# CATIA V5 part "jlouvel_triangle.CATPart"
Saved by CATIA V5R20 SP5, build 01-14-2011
Part number: Pièce 4_triangle
Bounding box of the stored display mesh (mm): x 0 to 5, y -113.66 to 130.843, z -78.426 to 5
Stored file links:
  E:\IAO_2010\iao\IAO_MMS_Groupe2\IAO_MMS_Groupe2\OK\jlouvel\jlouvel_iao\pièces cao catia ifma\jlouvel_triangle.CATPart
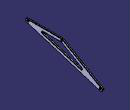
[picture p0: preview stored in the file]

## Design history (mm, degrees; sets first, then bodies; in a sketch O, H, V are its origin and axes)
Body1 (main body)
  Sketch1 on yz-plane, origin (0, 0, 0), H (0, 1, 0), V (0, 0, 1)
    line L1 (-113.6603, 5) -> (1.3397, 5)
    line L2 (1.3397, 5) -> (131.2436, -70)
    line L3 (131.2436, -70) -> (126.2436, -78.6603)
    line L4 (126.2436, -78.6603) -> (28.9711, -22.5)
    line L5 (28.9711, -22.5) -> (-1.3397, -5)
    line L6 (-1.3397, -5) -> (-113.6603, -5)
    line L7 (-113.6603, -5) -> (-113.6603, 5)
    length L7 = 10
    length L3 = 10
    length L1 = 115
    angle L2 L1 = 150
    distance L2 O = 5
    angle L5 L6 = 150
    length L5 = 35
    length L2 = 150
    horizontal: L1 H, L6 H
    perpendicularity: L3 L2
    vertical: L7 V
    parallelism: L2 L4
    symmetry: L6 L1 H
  Pad1: profile Sketch1, direction (1, 0, 0), length 5
  Sketch2 on yz-plane, origin (0, 0, 0), H (0, 1, 0), V (0, 0, 1)
    circle A1 centre (122.6814, -70.8301) radius 2
    point P1 (122.6814, -70.8301)
    circle A2 centre (0, 0) radius 2
    point P2 (0, -2)
    circle A3 centre (-106.6603, 0) radius 2
    point P3 (-106.6603, 0)
    reference projected line E1 (15.1795, -14.5374) -> (122.5833, -76.547) from edge [face of Pad1 from Sketch1.L4 | end face of Pad1]
    reference projected line E2 (86.6174, -147.2947) -> (91.6174, -138.6345) from edge [face of Pad1 from Sketch1.L3 | end face of Pad1]
    reference projected line E3 (-113.6603, 5) -> (-113.6603, -5) from edge [face of Pad1 from Sketch1.L7 | end face of Pad1]
    distance A1 E1 = 3
    radius A1 = 2
    distance P1 E2 = 7
    distance P3 E3 = 7
    radius A3 = 2
    radius A2 = 2
    coincidence: A2 P2, P2 V, P3 H
  Pocket1: profile Sketch2, direction (-1, 0, 0), through (limit type 6)
  Sketch3 on end face of Pad1, origin (5, 0, 0), H (0, 1, 0), V (0, 0, 1)
    line L1 (-42.8868, -5) -> (27.1132, -56.9615)
    point P2 (27.1132, -56.9615)
    line L2 (-42.8868, -5) -> (-2.8868, -5)
    point P3 (-2.8868, -5)
    line L3 (-2.8868, -5) -> (27.1132, -56.9615)
    point P4 (27.1132, -56.9615)
    reference projected point E1 (-2.8868, -5) from vertex [face of Pad1 from Sketch1.L5 | end face of Pad1 | face of Pad1 from Sketch1.L6]
    reference projected line E2 (-2.8868, -5) -> (14.6132, -35.3109) from edge [face of Pad1 from Sketch1.L5 | end face of Pad1]
    length L3 = 60
    length L2 = 40
    horizontal: L2 H
    coincidence: P4 L1, L3 P2, P3 E1, L3 E2, P2 P4
  Pad2: profile Sketch3, direction (-1, 0, 0), length 5, deactivated
  Fillet1: radius 5, on edge [face of Pad1 from Sketch1.L6 | face of Pad2 from Sketch3.L1]; edge [face of Pad2 from Sketch3.L1 | face of Pad1 from Sketch1.L4], deactivated
  Sketch4 on face of Pad2, origin (5, 0, 0), H (0, 1, 0), V (0, 0, 1)
    point P1 (-113.6603, -5)
    line L1 (-113.6603, -5) -> (126.2436, -78.6603)
    point P2 (126.2436, -78.6603)
    line L2 (126.2436, -78.6603) -> (87.5444, -56.3173)
    line L3 (87.5444, -56.3173) -> (-79.5907, -5)
    line L4 (-79.5907, -5) -> (-113.6603, -5)
    reference projected line E1 (-72.1132, -5) -> (-2.8868, -5) from edge [face of Pad1 from Sketch1.L6 | face of Pad2]
    reference projected line E2 (27.9904, -21.9338) -> (122.5833, -76.547) from edge [face of Pad1 from Sketch1.L4 | face of Pad2]
    reference projected point E3 (126.2436, -78.6603) from vertex [face of Pad1 from Sketch1.L3 | end face of Pad1 | face of Pad1 from Sketch1.L4]
    reference projected point E4 (-113.6603, -5) from vertex [face of Pad1 from Sketch1.L6 | end face of Pad1 | face of Pad1 from Sketch1.L7]
    distance L3 L1 = 10
    horizontal: L4 H
    coincidence: L4 E1, L2 E2, P2 E3, P1 E4
    parallelism: L3 L1
  Pad3: profile Sketch4, direction (-1, 0, 0), length 5
  Fillet2: radius 3, on edge [face of Pad3 from Sketch4.L3 | face of Pad1 from Sketch1.L6]; edge [face of Pad1 from Sketch1.L5 | face of Pad1 from Sketch1.L6]; edge [face of Pad1 from Sketch1.L4 | face of Pad3 from Sketch4.L3]
  Fillet3: radius 1, on face of Pad3 (x2); edge [face of Pad3 from Sketch4.L1 | face of Pad1 from Sketch1.L7]; edge [face of Pad1 from Sketch1.L7 | face of Pad1 from Sketch1.L1]; edge [face of Pad1 from Sketch1.L3 | face of Pad3 from Sketch4.L1]; edge [face of Pad1 from Sketch1.L2 | face of Pad1 from Sketch1.L3]; edge [face of Pad1 from Sketch1.L1 | face of Pad1 from Sketch1.L2]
